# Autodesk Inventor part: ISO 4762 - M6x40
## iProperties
Created: 2001-08
Part Number: ISO 4762 - M6x40
Catalog Web Link: file:///D:/Program%20Files/Autodesk/Inventor%205/Content/Iso/index.htm?doNavigateId=932883F9-F3A7-4770-8571-ED868C9DA26C|59A1F6498E2642A8B7EAC24285D28418|true
Description: Hexagon Socket Head Cap Screw
Document SubType Name: Standard Catalog Part
Standard: ISO 4762 - M6x40
Designer: Martin Budgell
Control State: 0
Master: False
Checked Out: False
Length Units: 11269
Angle Units: 11279
Time Units: 11290
Mass Units: 11283
Shininess: 3
Angle Display Precision: 2
Document Length Units: 11269
Document Angle Units: 11279
Document Time Units: 11290
Document Mass Units: 11283
Document Length Units Precision: 3
Document Angle Units Precision: 2
Compacted: True
CLASSIFICATION: 31161501 un/spsc
MANUFACTURER: ISO Standard System
Density: 0.0
Volumn: 0.0
Area: 0.0
PropertySet Name: Model Information
Author: Martin Budgell
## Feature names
1. Base1
